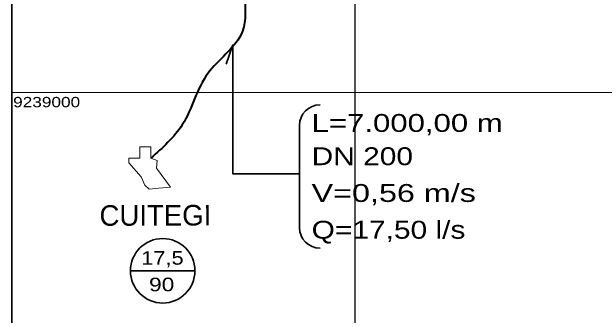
# Model space of a CAD drawing. Extents: x 0 to 1682, y 0 to 1188.
# Drawn here: x 952.3 to 1062.2, y 513.3 to 569.6 of the extents above; entities that cross this region are included whole.
import ezdxf
from ezdxf.enums import TextEntityAlignment as Align

# ---------------------------------------------------------------- set-up
doc = ezdxf.new("R2010")
doc.units = 0
doc.header["$LTSCALE"] = 1.3
doc.linetypes.add('DOT_DASHED', pattern=[7.7, 5, -1.2, 0.3, -1.2])
for name, color, linetype, lineweight in [('1', 7, 'DOT_DASHED', 13), ('6', 7, 'Continuous', 40), ('63', 7, 'Continuous', 25), ('8', 7, 'Continuous', 35), ('9', 7, 'Continuous', 40)]:
    doc.layers.add(name, color=color, linetype=linetype, lineweight=lineweight)

msp = doc.modelspace()

# ---------------------------------------------------------------- linework, layer by layer
at = {"layer": '1', "linetype": 'Continuous'}
msp.add_lwpolyline([(978.11, 542.421), (978.11, 544.482), (976.049, 544.482), (976.049, 542.421), (973.989, 542.421), (973.989, 541.531), (976.305, 538.913), (976.97, 537.4), (977.782, 536.626), (979.554, 536.81), (981.726, 537.036), (979.148, 540.572), (979.296, 541.974)], close=True, dxfattribs=at)
at = {"layer": '6'}
msp.add_spline([(1016.97, 601.589), (1003.954, 598.568), (997.364, 589.92), (994.779, 579.078), (994.779, 565.267), (988.706, 558.168), (983.925, 548.616), (978.11, 542.421)], degree=3, dxfattribs=at)
at = {"layer": '63'}
msp.add_line((1016.026, 427.142), (1016.026, 783.93), dxfattribs=at)
at = {"layer": '63', "lineweight": 13}
msp.add_line((1640.404, 554.567), (952.314, 554.567), dxfattribs=at)
at = {"layer": '63', "lineweight": 35}
msp.add_lwpolyline([(1640.404, 427.142), (952.314, 427.142), (952.314, 783.93)], dxfattribs=at)
at = {"layer": '8'}
msp.add_line((1005.667, 529.52), (1005.667, 548.476), dxfattribs=at)
msp.add_lwpolyline([(1005.667, 539.477), (993.317, 539.477), (993.317, 563.438), (992.051, 559.872)], dxfattribs=at)
for centre, start, end in [((1009.489, 548.476), 90, 180), ((1009.489, 548.476), 90, 180), ((1009.489, 548.476), 90, 180), ((1009.489, 529.52), 180, 270)]:
    msp.add_arc(centre, 3.823, start, end, dxfattribs=at)
at = {"layer": '9', "lineweight": 35}
msp.add_line((974.312, 521.505), (986.283, 521.505), dxfattribs=at)
msp.add_circle((980.298, 521.505), 5.985, dxfattribs=at)

# ---------------------------------------------------------------- texts
at = {"layer": '63', "width": 1.25}
msp.add_text('9239000', height=1.911, dxfattribs=at).set_placement((952.549, 551.864))
at = {"layer": '8'}
for s, width, p in [('L=7.000,00 m', 1.3, (1007.918, 547.284)), ('DN 200', 1.25, (1007.918, 541.105)), ('V=0,56 m/s', 1.35, (1007.918, 534.281)), ('Q=17,50 l/s', 1.25, (1007.918, 527.457))]:
    msp.add_text(s, height=3.319, dxfattribs=dict(at, width=width)).set_placement(p)
at = {"layer": '9'}
msp.add_text('CUITEGI', height=3.823, rotation=0.17, dxfattribs=at).set_placement((968.584, 529.852))
for s, width, p in [('17,5', 1.2, (980.247, 522.628)), ('90', 1.25, (980.112, 517.699))]:
    msp.add_text(s, height=2.52, rotation=0.17, dxfattribs=dict(at, width=width)).set_placement(p, align=Align.CENTER)

doc.saveas('drawing.dxf')
